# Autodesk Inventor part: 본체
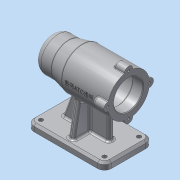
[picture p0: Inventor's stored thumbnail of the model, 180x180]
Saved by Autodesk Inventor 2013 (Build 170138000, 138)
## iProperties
Created: 2019-07
Part Number: 본체
Material: 알루미늄 6061
Document SubType Name: Modeling
Designer: dg
Mass: 651.004 g
Surface Area: 657.622 cm^2
Volume: 240.223 cm^3
Density: 2.71 g/cm^3
Author: dg
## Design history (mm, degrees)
sketch "스케치1"
  geometry: L1 (-56, -35)-(56, -35); L2 (56, -35)-(56, 35); L3 (56, 35)-(-56, 35); L4 (-56, 35)-(-56, -35); L5 (-56, -35)-(56, 35); L6 (56, -35)-(-56, 35); 1 further point
  constraints: 12 end point, 2 midpoint, 2 parallel, 1 horizontal, 1 perpendicular
  dimensions: "d0" = 112 distance of L2.end L3.end; "d2" = 70 distance of L1.end L2.end
extrude "돌출1" new body sketch "스케치1" distance "d3" = 10; taper "d4" = 0 deg
fillet "모깎기1" dims "d5" = 10
sketch "스케치2"
  geometry: A1 r 10 centre (46, -25) between (46, -35) and (56, -25) reference; A2 r 10 centre (46, 25) between (56, 25) and (46, 35) reference; A3 r 10 centre (-46, 25) between (-46, 35) and (-56, 25) reference; A4 r 10 centre (-46, -25) between (-56, -25) and (-46, -35) reference; 1 further point
hole "구멍1" sketch "스케치2" at (-46, 25), (46, 25), (46, -25), (-46, -25) diameter "d6" = 6; stored, may be unused: countersink angle "d10" = 90 deg, drill point angle "d12" = 118 deg; dims "d7" = 6, "d8" = 4, "d9" = 2, "d11" = 10
node "작업 평면1"
sketch "스케치4"
  geometry: L1 (-10, 0)-(-10, 10) reference; L2 (-10, 10)-(0, 10) reference; L3 (0, 10)-(0, 0) reference; L4 (0, 0)-(-10, 0) reference; L5 (-10, 0)-(-10, 10) reference; L6 (92, 0)-(92, 10) reference; L7 (92, 0)-(0, 0) reference; L8 (0, 10)-(0, 0) reference; L9 (92, 10)-(0, 10) reference; L10 (92, 0)-(92, 10) reference; L11 (92, 10)-(102, 10) reference; L12 (102, 10)-(102, 0) reference; L13 (102, 0)-(92, 0) reference; L14 (92, 0)-(92, 10) reference; L15 (102, 0)-(102, 80); L16 (102, 80)-(-10, 80); L17 (-10, 80)-(-10, 105); L18 (-10, 105)-(15, 105); L19 (15, 105)-(35, 110); L20 (35, 110)-(102, 110); L21 (102, 110)-(102, 80); 1 further point
  constraints: 14 end point, 3 parallel, 3 perpendicular
  dimensions: "d51" = 80 distance of L12.end L15.end; "d57" = 50 diameter of L18 L16; "d58" = 60 diameter of L20 L16; "d60" = 25 distance from line of L18.end L17; "d61" = 45 distance from line of L19.end L17; "d62" = 112 distance of L15.end L16.end
revolve "회전1" sketch "스케치4" stored, may be unused: angle "d65" = 90 deg
fillet "모깎기2" dims "d66" = 10
sketch "스케치5"
  geometry: C1 r 30 at (0, 0) reference; C2 r 21 at (0, 0); 1 further point
  constraints: 1 centre point, 1 coincident
  dimensions: "d67" = 42 diameter of C2
extrude "돌출2" cut sketch "스케치5" distance "d69" = 15; taper "d70" = 0 deg
sketch "스케치6"
  geometry: C1 r 21 at (0, 0) reference; C2 r 24 at (0, 0); 1 further point
  constraints: 1 centre point, 1 coincident
  dimensions: "d71" = 48 diameter of C2
extrude "돌출3" cut sketch "스케치6" distance "d74" = 54; taper "d75" = 0 deg
sketch "스케치7"
  geometry: C1 r 24 at (0, 0) reference; C2 r 21 at (0, 0); 1 further point
  constraints: 1 centre point, 1 coincident
  dimensions: "d76" = 42 diameter of C2
extrude "돌출4" cut sketch "스케치7" distance "d78" = 12; taper "d79" = 0 deg
sketch "스케치8"
  geometry: C1 r 21 at (0, 0) reference; C2 r 17.5 at (0, 0); 1 further point
  constraints: 1 centre point, 1 coincident
  dimensions: "d80" = 35 diameter of C2
extrude "돌출5" cut sketch "스케치8" distance "d82" = 18; taper "d83" = 0 deg
sketch "스케치9"
  geometry: C1 r 17.5 at (0, 0) reference; C2 r 16 at (0, 0); 1 further point
  constraints: 1 centre point, 1 coincident
  dimensions: "d84" = 32 diameter of C2
extrude "돌출6" cut sketch "스케치9" distance "d86" = 4; taper "d87" = 0 deg
sketch "스케치10"
  geometry: C1 r 16 at (0, 0) reference; C2 r 10.5 at (0, 0); 1 further point
  constraints: 1 centre point, 1 coincident
  dimensions: "d88" = 21 diameter of C2
extrude "돌출7" cut sketch "스케치10" distance "d90" = 3; taper "d91" = 0 deg
fillet "모깎기3" dims "d92" = 3
fillet "모깎기4" dims "d93" = 3
fillet "모깎기5" dims "d94" = 0.3
sketch "스케치11"
  geometry: L1 (0, 0)-(-30, 0); C1 r 6 at (-30, 0); 1 further point
  constraints: 2 end point, 1 centre point, 1 coincident, 1 horizontal, 1 horizontal alignment, 1 other
  dimensions: "d97" = 6 radius of C1
extrude "돌출8" join sketch "스케치11" distance "d99" = 16; taper "d100" = 0 deg
fillet "모깎기7" dims "d101" = 3
fillet "모깎기8" dims "d102" = 1
sketch "스케치12"
  geometry: A1 r 6 centre (0, 0) between (-0.171, 5.998) and (-0.171, -5.998) reference; 1 further point
hole "구멍2" sketch "스케치12" at (0, 0) diameter "d103" = 3.242; stored, may be unused: countersink angle "d107" = 90 deg, drill point angle "d109" = 118 deg; dims "d104" = 8, "d105" = 4, "d106" = 2, "d108" = 11
fillet "모깎기9" dims "d113" = 3
fillet "모깎기10" dims "d114" = 1
sketch "스케치13"
  geometry: L1 (0, 105)-(0, 55) reference; L2 (102, 86.771)-(89, 86.771) reference; L3 (102, 109.226)-(102, 86.771) reference; L4 (89, 109.226)-(102, 109.226) reference; L5 (85, 109.871)-(85, 109.871) reference; L6 (102, 109.226)-(89, 109.226) reference; L7 (102, 86.771)-(102, 109.226) reference; L8 (89, 86.771)-(102, 86.771) reference; L9 (85, 77.221)-(85, 82.779) reference; L10 (102, 73.229)-(89, 73.229) reference; L11 (102, 50.774)-(102, 73.229) reference; L12 (89, 50.774)-(102, 50.774) reference; L13 (85, 50.129)-(85, 50.129) reference; L14 (102, 50.774)-(89, 50.774) reference; L15 (102, 73.229)-(102, 50.774) reference; L16 (89, 73.229)-(102, 73.229) reference; L17 (85, 82.779)-(85, 77.221) reference; L18 (92, 0)-(92, 10) reference; L19 (92, 0)-(0, 0) reference; L20 (0, 10)-(0, 0) reference; L21 (92, 10)-(0, 10) reference; L22 (-10, 10)-(0, 10) reference; L23 (0, 10)-(0, 0) reference; L24 (0, 0)-(-10, 0) reference; L25 (-10, 0)-(-10, 10) reference; L26 (92, 10)-(102, 10) reference; L27 (102, 10)-(102, 0) reference; L28 (102, 0)-(92, 0) reference; L29 (92, 0)-(92, 10) reference; L30 (35, 110)-(85, 110) reference; L31 (35, 50)-(85, 50) reference; L32 (15, 55)-(35, 50) reference; L33 (0, 55)-(15, 55) reference; L34 (26.015, 54)-(10, 10); L35 (26.015, 54)-(77, 54); L36 (77, 54)-(77, 10); L37 (77, 10)-(10, 10); 9 further points; 2 other entities
  constraints: 8 end point, 2 point on line, 1 collinear, 1 parallel, 1 perpendicular, 10 other
  dimensions: "d115" = 25 distance between parallel lines of L27 L36; "d116" = 20 distance from line of L25 L34.end; "d117" = 110 deg angle of L22 L34; "d118" = 44 distance between parallel lines of L21 L35
extrude "돌출9" join sketch "스케치13" stored distance "d119" = 8; taper "d120" = 0 deg
node "작업 평면2"
sketch "스케치14"
  geometry: L1 (-10, 47)-(-10, 53) reference; L2 (-10, 50)-(-10, 60) reference; L3 (0, 53)-(-10, 53) reference; L4 (-10, 50)-(-10, 60) reference; L5 (-10, 60)-(0, 60) reference; L6 (0, 60)-(0, 50) reference; L7 (0, 50)-(-10, 50) reference; L8 (0, 50)-(-10, 50) reference; L9 (0, 50)-(0, 0) reference; L10 (-10, 0)-(0, 0) reference; L11 (-10, 50)-(-10, 0) reference; L12 (-10, -10)-(-10, 0) reference; L13 (-10, 0)-(0, 0) reference; L14 (0, 0)-(0, -10) reference; L15 (0, -10)-(-10, -10) reference; L16 (-52.659, 21)-(-10, 21) reference; L17 (-10, 29)-(-52.659, 29) reference; L18 (-57.334, 5.346)-(-10, -3); L19 (-10, -3)-(-10, 53); L20 (-57.334, 44.654)-(-10, 53); A1 r 30 centre (-80, 25) between (-50.268, 29) and (-50.268, 21) reference; A2 r 30 centre (-80, 25) between (-57.334, 5.346) and (-57.334, 44.654); 1 further point
  constraints: 6 end point, 2 point on circle, 2 point on line, 1 centre point, 1 coincident
  dimensions: "d125" = 7 distance from line of L5 L19.end; "d126" = 7 distance from line of L15 L18.end; "d127" = 100 deg angle of L2 L20; "d128" = 100 deg angle of L11 L18; "d146" = 30 radius of A2
extrude "돌출10" join sketch "스케치14" stored distance "d132" = 8; taper "d133" = 0 deg
fillet "모깎기11" dims "d134" = 3
chamfer "모따기1" distance "d136" = 1; stored, may be unused: second distance "d137" = 2, angle "d138" = 45 deg
chamfer "모따기2" distance "d139" = 3; stored, may be unused: second distance "d140" = 2, angle "d141" = 45 deg
node "작업 평면3"
sketch "스케치15"
  geometry: L1 (56, 86.771)-(56, 109.226) reference; L2 (56, 58)-(56, 102) reference; L3 (56, 50.774)-(56, 73.229) reference; L4 (56, 80)-(-10.631, 80); L5 (56, 116)-(56, 110.171) reference; 3 further points
  constraints: 2 coincident, 2 end point, 1 midpoint, 1 perpendicular, 1 point on line, 1 other
  dimensions: "d143" = 42 distance from line of point (14, 80) L5
feature "엠보싱1" sketch "스케치15" dims "d144" = 0.5, "d145" = 0
fillet "모깎기13" dims "d147" = 3
fillet "모깎기14" dims "d148" = 3
node "솔리드1"
pattern_circular "원형 패턴1" dims angle "d111" = 360 deg
node "투영된 루프1"
node "투영된 루프2"
node "투영된 루프3"
node "투영된 루프5"
node "투영된 루프6"
node "투영된 루프7"
node "투영된 루프8"
node "투영된 루프9"
node "투영된 루프10"
node "투영된 루프11"
node "투영된 루프12"
